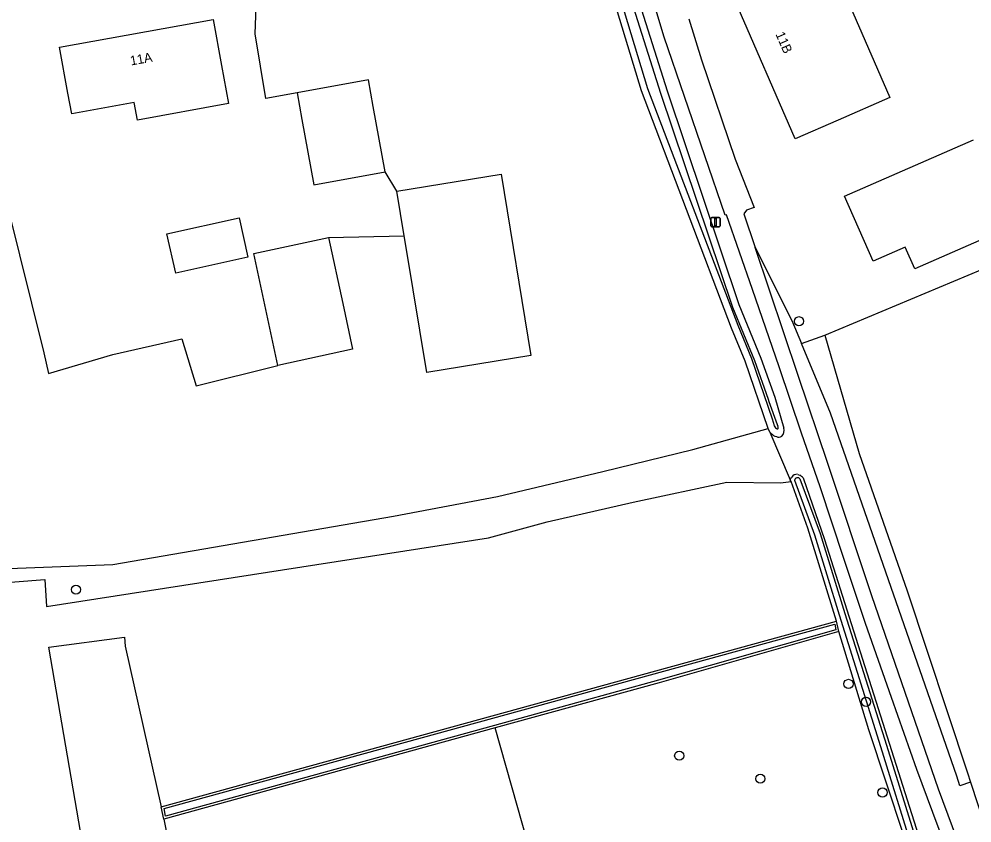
# Model space of a CAD drawing. Extents: x 162515 to 163909, y 388494 to 389773.
# Drawn here: x 163100.4 to 163202.2, y 388872.2 to 388958.1 of the extents above; entities that cross this region are included whole.
import ezdxf

# ---------------------------------------------------------------- set-up
doc = ezdxf.new("R2010")
doc.units = 0
for name, color, linetype in [('IMGEO_Berm_groen', 7, 'Continuous'), ('IMGEO_Boom', 7, 'Continuous'), ('IMGEO_Grasland_agrarisch', 7, 'Continuous'), ('IMGEO_Loofbos', 7, 'Continuous'), ('IMGEO_Oever', 7, 'Continuous'), ('IMGEO_Pand', 7, 'Continuous'), ('IMGEO_Pand_nummerreeks', 7, 'Continuous'), ('IMGEO_Rijbaan_lokaal_gesloten', 7, 'Continuous'), ('IMGEO_Terreindeel_onvherhard', 7, 'Continuous'), ('IMGEO_Verkeersbordpaal', 7, 'Continuous'), ('IMGEO_Voetpad_onverhard', 7, 'Continuous'), ('IMGEO_Waterloop', 7, 'Continuous')]:
    doc.layers.add(name, color=color, linetype=linetype)

msp = doc.modelspace()

# ---------------------------------------------------------------- linework, layer by layer
at = {"layer": 'IMGEO_Berm_groen'}
for points in [[(163161.38, 388976.5), (163169.62, 388950.37), (163177.3, 388927.55), (163179.64, 388921.83), (163181.12, 388917.66), (163182.1, 388914.36)], [(163179.03, 388933.65), (163182.95, 388925.86), (163183.98, 388923.38)], [(163180.59, 388913.92), (163182.78, 388908.83)], [(163180.74, 388913.77), (163180.59, 388913.92)], [(163182.78, 388908.83), (163182.85, 388908.98), (163182.93, 388909.11)], [(163183.57, 388909.41), (163183.78, 388909.34)], [(163184.15, 388909.02), (163186.42, 388902.45), (163196.94, 388869.35), (163199.73, 388861.79), (163204.22, 388848.72), (163218.61, 388813.51), (163219.55, 388810.66), (163218.63, 388810.31)], [(163202.02, 388876.51), (163203.59, 388871.75)]]:
    msp.add_lwpolyline(points, dxfattribs=at)
for centre, radius, start, end in [((163181.23, 388914.13), 0.899, 314.7973, 14.7484), ((163181.73, 388914.79), 1.42, 226.0932, 252.345), ((163181.54, 388914.01), 0.617, 247.4853, 302.2266), ((163183.52, 388908.7), 0.718, 86.1687, 144.849), ((163182.61, 388907.62), 2.09, 42.1611, 55.8358)]:
    msp.add_arc(centre, radius, start, end, dxfattribs=at)
at = {"layer": 'IMGEO_Boom'}
for centre in [(163183.71, 388925.77), (163106.49, 388897.09), (163189, 388887.02), (163190.87, 388885.1), (163170.92, 388879.35), (163179.58, 388876.89), (163192.63, 388875.42)]:
    msp.add_circle(centre, 0.489, dxfattribs=at)
at = {"layer": 'IMGEO_Grasland_agrarisch'}
for points in [[(163180.43, 388914.3), (163177.97, 388921.49), (163176.52, 388925.03), (163166.88, 388950.37), (163159.58, 388974.48), (163126.1, 388968.98)], [(163130.11, 388950.18), (163126.78, 388949.58), (163125.62, 388956.46), (163126.1, 388968.98)], [(163092.58, 388964.47), (163103.05, 388922.38), (163103.55, 388920.18), (163110.43, 388922.2), (163117.79, 388923.89), (163119.33, 388918.85), (163128.06, 388921.05)], [(163140.77, 388939.65), (163139.52, 388941.72)], [(163186.47, 388924.27), (163218.62, 388937.76)], [(163133.46, 388934.72), (163141.55, 388934.88)], [(163054.78, 388897.65), (163110.42, 388899.79), (163140.42, 388904.94), (163151.53, 388907.04), (163162.75, 388909.72), (163172.37, 388912.05), (163180.43, 388914.3)], [(163054.88, 388896.66), (163091.26, 388897.24), (163103.16, 388898.16), (163103.33, 388895.29), (163150.54, 388902.64), (163156.82, 388904.32), (163166.01, 388906.45), (163176.02, 388908.58), (163181.74, 388908.52), (163182.86, 388908.65)], [(163187.72, 388893.72), (163184.67, 388903.66), (163182.86, 388908.65)], [(163115.6, 388873.88), (163187.72, 388893.72)]]:
    msp.add_lwpolyline(points, dxfattribs=at)
at = {"layer": 'IMGEO_Loofbos'}
for points in [[(163187.97, 388892.62), (163168.79, 388887.15), (163151.27, 388882.33)], [(163218.14, 388810.13), (163217.43, 388812.61), (163206.05, 388840.04), (163203.18, 388847.41), (163196.75, 388865.23), (163191.17, 388882.12), (163187.97, 388892.62)], [(163151.27, 388882.33), (163115.86, 388872.57)], [(163175.36, 388797.22), (163151.27, 388882.33)]]:
    msp.add_lwpolyline(points, dxfattribs=at)
at = {"layer": 'IMGEO_Oever'}
msp.add_lwpolyline([(163187.97, 388892.62), (163187.72, 388893.72)], dxfattribs=at)
at = {"layer": 'IMGEO_Pand'}
for points in [[(163188.13, 388961.83), (163193.43, 388949.67), (163187.89, 388947.26), (163183.3, 388945.26), (163176.85, 388960.08)], [(163106.04, 388947.92), (163105.64, 388950.12), (163104.74, 388955.04), (163121.14, 388958.02), (163122.04, 388953.1), (163122.78, 388949.04), (163113.05, 388947.27), (163112.71, 388949.14), (163106.04, 388947.92)], [(163139.52, 388941.72), (163138.25, 388948.71), (163137.73, 388951.57), (163130.11, 388950.18)], [(163130.11, 388950.18), (163130.63, 388947.32), (163131.9, 388940.33), (163139.52, 388941.72)], [(163206.32, 388935.86), (163196.07, 388931.36), (163195.05, 388933.68), (163191.62, 388932.17), (163188.57, 388939.12), (163202.34, 388945.16)], [(163140.77, 388939.65), (163151.89, 388941.48), (163155.08, 388922.1), (163143.95, 388920.28), (163141.76, 388933.64), (163141.55, 388934.88)], [(163141.55, 388934.88), (163140.77, 388939.65)], [(163123.92, 388936.83), (163124.86, 388932.6), (163117.15, 388930.89), (163116.21, 388935.12), (163123.92, 388936.83)], [(163128.06, 388921.05), (163125.48, 388932.99), (163133.46, 388934.72)], [(163133.46, 388934.72), (163134.98, 388927.67), (163136.04, 388922.78), (163128.06, 388921.05)]]:
    msp.add_lwpolyline(points, dxfattribs=at)
at = {"layer": 'IMGEO_Rijbaan_lokaal_gesloten'}
for points in [[(163223.17, 388803.99), (163223, 388804.99), (163221.55, 388810.03), (163196.28, 388877.87), (163193.58, 388885.57), (163190.81, 388893.47), (163188.49, 388900.41), (163185.96, 388908.08), (163183.98, 388913.82), (163181.6, 388920.91), (163178.74, 388929.17), (163175.98, 388937.13), (163175.83, 388937.09), (163169.3, 388956.12), (163167.23, 388963.02), (163163.94, 388974.74), (163163.44, 388977.02)], [(163171.93, 388958.09), (163173.3, 388953.69), (163176.91, 388943.07), (163178.91, 388937.91), (163178.09, 388937.63), (163177.83, 388937.24), (163179.03, 388933.65)], [(163224.51, 388805.33), (163223.19, 388809.82), (163215.39, 388831.04), (163211.89, 388840.11), (163205.17, 388858.13), (163198.6, 388875.79), (163191.5, 388896.44), (163186.8, 388910.56), (163183.64, 388919.96), (163179.03, 388933.65)]]:
    msp.add_lwpolyline(points, dxfattribs=at)
at = {"layer": 'IMGEO_Terreindeel_onvherhard'}
for points in [[(163180.59, 388913.92), (163180.43, 388914.3)], [(163182.86, 388908.65), (163182.78, 388908.83)]]:
    msp.add_lwpolyline(points, dxfattribs=at)
at = {"layer": 'IMGEO_Verkeersbordpaal'}
for p, q in [((163174.3, 388935.96), (163174.3, 388936.76)), ((163174.3, 388936.76), (163174.3, 388935.96)), ((163174.4, 388936.86), (163175.19, 388936.86)), ((163175.19, 388936.86), (163174.4, 388936.86)), ((163175.29, 388936.76), (163175.29, 388935.96)), ((163175.29, 388935.96), (163175.29, 388936.76)), ((163175.19, 388935.86), (163174.4, 388935.86)), ((163174.4, 388935.86), (163175.19, 388935.86))]:
    msp.add_line(p, q, dxfattribs=at)
msp.add_lwpolyline([(163174.72, 388936.73), (163174.87, 388936.73), (163174.87, 388935.98), (163174.72, 388935.98), (163174.72, 388936.73)], dxfattribs=at)
for centre, start, end in [((163174.4, 388936.76), 90, 180), ((163174.4, 388936.76), 90, 180), ((163175.19, 388936.76), 0, 90), ((163175.19, 388936.76), 360, 90), ((163174.4, 388935.96), 180, 270), ((163174.4, 388935.96), 180, 270), ((163175.19, 388935.96), 270, 0), ((163175.19, 388935.96), 270, 0)]:
    msp.add_arc(centre, 0.1, start, end, dxfattribs=at)
at = {"layer": 'IMGEO_Voetpad_onverhard'}
for points in [[(162992.03, 388880.14), (162993.09, 388878.08), (162993.95, 388876.52), (163000.59, 388868.45), (163013.34, 388853.63), (163015.61, 388845.97), (163017.67, 388844.2), (163104.81, 388834.21), (163113.39, 388833.94), (163103.59, 388890.93), (163111.66, 388892.01), (163111.76, 388891.05), (163115.6, 388873.88)], [(163115.86, 388872.57), (163115.6, 388873.88)], [(163115.86, 388872.57), (163121.94, 388842.23)]]:
    msp.add_lwpolyline(points, dxfattribs=at)
at = {"layer": 'IMGEO_Waterloop'}
for points in [[(163181.15, 388914.48), (163181.11, 388914.6), (163180.87, 388915.31), (163178.67, 388921.75), (163177.21, 388925.3), (163167.58, 388950.61), (163160.1, 388975.32), (163126.72, 388969.84), (163126.65, 388970.32), (163126.64, 388970.35), (163160.65, 388976.36), (163160.67, 388976.28), (163168.92, 388950.14), (163176.61, 388927.29), (163178.95, 388921.57), (163180.42, 388917.43), (163180.49, 388917.18)], [(163183.98, 388923.38), (163186.47, 388924.27)], [(163186.47, 388924.27), (163190.15, 388911.65), (163195.26, 388896.96), (163201.7, 388877.51), (163202.02, 388876.51)], [(163202.02, 388876.51), (163200.88, 388876.13), (163200.58, 388877.17), (163187.09, 388915.93), (163183.98, 388923.38)], [(163180.49, 388917.18), (163181.39, 388914.73), (163181.45, 388914.54)], [(163218.02, 388811.08), (163217.99, 388811.23), (163217.98, 388811.38), (163217.97, 388811.49), (163217.94, 388812.11), (163217.6, 388813.21), (163215.75, 388817.92), (163210.68, 388830.11), (163206.29, 388841.1), (163203.31, 388848.18), (163201.82, 388852.63), (163197.37, 388865.27), (163195.84, 388869.4), (163192.45, 388880.31), (163188.02, 388894.35), (163185.39, 388902.9), (163183.25, 388908.76)], [(163183.44, 388909.04), (163183.54, 388909.08), (163183.58, 388909.08), (163183.65, 388909.06), (163183.78, 388908.98), (163183.8, 388908.92), (163185.98, 388903.1), (163188.61, 388894.53), (163193.05, 388880.49), (163196.43, 388869.6), (163197.95, 388865.48), (163202.41, 388852.83), (163203.89, 388848.4), (163206.86, 388841.33), (163211.26, 388830.35), (163216.33, 388818.16), (163218.18, 388813.41), (163218.83, 388811.33)], [(163187.65, 388892.81), (163168.72, 388887.41), (163151.2, 388882.58), (163116.06, 388872.9), (163115.9, 388873.69), (163187.53, 388893.39), (163187.65, 388892.81)]]:
    msp.add_lwpolyline(points, dxfattribs=at)
for centre, radius, start, end in [((163181.54, 388914.66), 0.434, 204.8874, 237.4401), ((163181.4, 388914.46), 0.189, 242.0998, 283.1122), ((163181.42, 388914.34), 0.0672, 290.0696, 3.3433), ((163180.77, 388914.33), 0.717, 0.8382, 16.6541), ((163183.63, 388908.71), 0.384, 120.3604, 172.9137)]:
    msp.add_arc(centre, radius, start, end, dxfattribs=at)

# ---------------------------------------------------------------- texts
at = {"layer": 'IMGEO_Pand_nummerreeks'}
for s, rotation, p in [('11B', 293.5312, (163181.18, 388956.45)), ('11A', 10.3178, (163112.37, 388953.09))]:
    msp.add_text(s, height=1, rotation=rotation, dxfattribs=at).set_placement(p)

doc.saveas('drawing.dxf')
